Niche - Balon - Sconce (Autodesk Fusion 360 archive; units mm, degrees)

design "Elongated Sconce - Balon" references "Encalmo Grand", "Elongated Sconce - Helio"
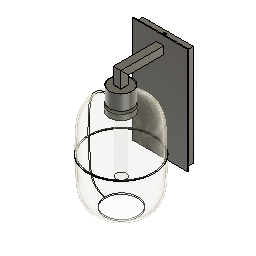
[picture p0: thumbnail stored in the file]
external_derived "ExternalDerived1" bodies "Socket Cover", "T9-Bulb", "Screw Bottom", "Knurled Shade Ring", "Screw Top", "Back Plate", "Sconce", "Socket - E26"
derived_instance "DerivedInstance1"
derived_instance "DerivedInstance2"
derived_instance "DerivedInstance3"
derived_instance "DerivedInstance4"
derived_instance "DerivedInstance5"
derived_instance "DerivedInstance6"
derived_instance "DerivedInstance7"
derived_instance "DerivedInstance8"
derived_instance "DerivedInstance9"
external_derived "ExternalDerived2" bodies "Encalmo Grand", "Encalmo Grand (1)"
align "Align1"
align "Align2"
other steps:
derived_base_feature "Derived Base Feature1" bodies "Socket Cover"
derived_base_feature "Derived Base Feature1" bodies "T9-Bulb"
derived_base_feature "Derived Base Feature1" bodies "Screw Bottom"
derived_base_feature "Derived Base Feature1" bodies "Knurled Shade Ring"
derived_base_feature "Derived Base Feature1" bodies "Screw Top"
derived_base_feature "Derived Base Feature1" bodies "Back Plate"
derived_base_feature "Derived Base Feature1" bodies "Sconce"
derived_base_feature "Derived Base Feature1" bodies "Socket - E26"
derived_base_feature "Derived Base Feature1" bodies "E26 Base", "Screw Bottom"
derived_base_feature "Derived Base Feature2" bodies "Encalmo Grand", "Encalmo Grand (1)"
create_component "CreateComponent1"
create_component "CreateComponent2"
create_component "CreateComponent3"
create_component "CreateComponent4"
create_component "CreateComponent5"
create_component "CreateComponent6"
create_component "CreateComponent7"
create_component "CreateComponent8"
create_component "CreateComponent9"
named bodies: "Back Plate", "Screw Top", "Knurled Shade Ring", "Sconce", "Encalmo Grand", "Encalmo Grand (1)", "Socket Cover", "Screw Bottom", "Socket - E26", "T9-Bulb", "E26 Base"

design "Encalmo Grand" references "Niche_Encalmo_Grand_Single_Pendant"
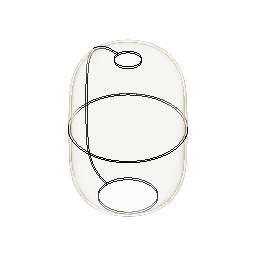
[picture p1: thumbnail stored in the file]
external_derived "ExternalDerived1" bodies "Encalmo Grand"
work_plane "WorkPlane1" AlongDistance -124.2212
split "Split1" bodies "Encalmo Grand (1)"
fillet "Fillet1" radius 0.0254
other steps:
derived_base_feature "Derived Base Feature" bodies "Encalmo Grand"
named bodies: "Encalmo Grand", "Encalmo Grand (1)"

design "Elongated Sconce - Helio"
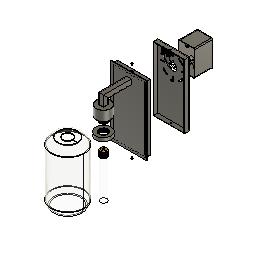
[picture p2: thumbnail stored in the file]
derived_base_feature "Derived Base Feature1" bodies "T9-Bulb", "Helio"
derived_base_feature "Derived Base Feature2" bodies "Back Plate", "Socket Cover", "Screw Top", "Screw Bottom", "Knurled Shade Ring", "Socket - E26"
derived_base_feature "Derived Base Feature3" bodies "E26 Base"
move "Move1"
component_from_bodies "Body->Comp1"
component_from_bodies "Body->Comp2"
component_from_bodies "Body->Comp3"
component_from_bodies "Body->Comp4"
component_from_bodies "Body->Comp5"
component_from_bodies "Body->Comp6"
component_from_bodies "Body->Comp7"
component_from_bodies "Body->Comp8"
component_from_bodies "Body->Comp9"
component_from_bodies "Body->Comp10"
derived_base_feature "Derived Base Feature5" bodies "screw1", "screw1 (1)", "Body1"
move "Move3"
move "Move4"
move "Move5"
move "Move6"
component_from_bodies "Body->Comp11"
component_from_bodies "Body->Comp12"
component_from_bodies "Body->Comp13"
component_from_bodies "Body->Comp14"
component_from_bodies "Body->Comp15"
component_from_bodies "Body->Comp16"
component_from_bodies "Body->Comp17"
component_from_bodies "Body->Comp18"
component_from_bodies "Body->Comp19"
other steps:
base_feature "Base Feature1" bodies "T9-Bulb"
base_feature "Base Feature1" bodies "E26 Base"
base_feature "Base Feature1" bodies "Body1"
base_feature "Base Feature1" bodies "Body1 (1) (1)"
base_feature "Base Feature1" bodies "Body9"
base_feature "Base Feature1" bodies "Body7"
base_feature "Base Feature1" bodies "Body6"
base_feature "Base Feature1" bodies "screw1"
base_feature "Base Feature1" bodies "Body4"
base_feature "Base Feature1" bodies "screw1 (1)"
base_feature "Base Feature1" bodies "Body1 (1)"
base_feature "Base Feature1" bodies "Helio"
base_feature "Base Feature1" bodies "Back Plate"
base_feature "Base Feature1" bodies "Knurled Shade Ring"
base_feature "Base Feature1" bodies "Screw Top"
base_feature "Base Feature1" bodies "Sconce"
base_feature "Base Feature1" bodies "Socket Cover"
base_feature "Base Feature1" bodies "Screw Bottom"
base_feature "Base Feature1" bodies "Socket - E26"
create_component "CreateComponent1"
remove_body "RemoveBody1"
create_component "CreateComponent2"
remove_body "RemoveBody2"
create_component "CreateComponent3"
remove_body "RemoveBody3"
create_component "CreateComponent4"
remove_body "RemoveBody4"
create_component "CreateComponent5"
remove_body "RemoveBody5"
create_component "CreateComponent6"
remove_body "RemoveBody6"
create_component "CreateComponent7"
remove_body "RemoveBody7"
create_component "CreateComponent8"
remove_body "RemoveBody8"
create_component "CreateComponent9"
remove_body "RemoveBody9"
create_component "CreateComponent10"
remove_body "RemoveBody10"
create_component "CreateComponent11"
remove_body "RemoveBody11"
create_component "CreateComponent12"
remove_body "RemoveBody12"
create_component "CreateComponent13"
remove_body "RemoveBody13"
create_component "CreateComponent14"
remove_body "RemoveBody14"
create_component "CreateComponent15"
remove_body "RemoveBody15"
create_component "CreateComponent16"
remove_body "RemoveBody16"
create_component "CreateComponent17"
remove_body "RemoveBody17"
create_component "CreateComponent18"
remove_body "RemoveBody18"
create_component "CreateComponent19"
remove_body "RemoveBody19"
named bodies: "T9-Bulb", "Helio", "Back Plate", "Socket Cover", "Screw Top", "Screw Bottom", "Knurled Shade Ring", "Socket - E26", "Body34", "Sconce", "E26 Base", "screw1", "screw1 (1)", "Body1", "Body1 (1)", "Body4", "Body6", "Body7", "Body1 (1) (1)", "Body9"

design "Niche_Encalmo_Grand_Single_Pendant"
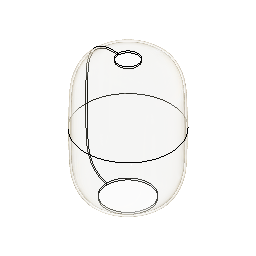
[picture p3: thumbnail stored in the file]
